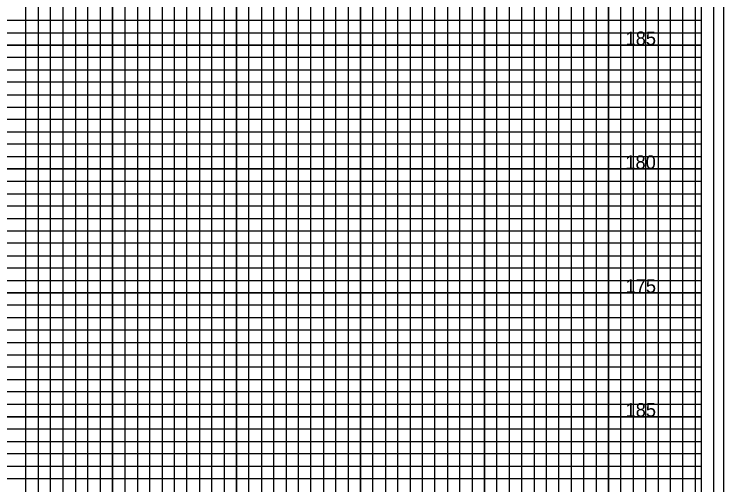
# Model space of a CAD drawing. Extents: x -4 to 103, y -2 to 280.
# Drawn here: x 74.78 to 103.4, y 173.9 to 192.9 of the extents above; entities that cross this region are included whole.
import ezdxf

# ---------------------------------------------------------------- set-up
doc = ezdxf.new("R2010")
doc.units = 0
for name, color, linetype in [('Exist XS Center Line Elevation Label', 7, 'Continuous'), ('Old_Level_63', 7, 'Continuous'), ('Prop XS Dump Level', 7, 'Continuous'), ('Prop XS SE Text', 7, 'Continuous'), ('Prop XS Subgrade Earthwork', 7, 'Continuous'), ('Sheet Plot Border Inside CELL', 7, 'Continuous'), ('Sheet Plot Border Outside CELL', 7, 'Continuous')]:
    doc.layers.add(name, color=color, linetype=linetype)

msp = doc.modelspace()

# ---------------------------------------------------------------- linework, layer by layer
at = {"layer": 'Exist XS Center Line Elevation Label'}
for points in [[(91.25, 141.65), (91.25, 205.075), (93.75, 205.075), (93.75, 141.65)], [(96.25, 141.65), (96.25, 205.075), (98.75, 205.075), (98.75, 141.65)], [(101.25, 141.65), (101.25, 205.075)], [(76.25, 141.65), (76.25, 203.65), (78.75, 203.65), (78.75, 141.65)], [(81.25, 141.65), (81.25, 203.65), (83.75, 203.65), (83.75, 141.65)], [(86.25, 141.65), (86.25, 203.65), (88.75, 203.65), (88.75, 141.65)], [(0, 189.15), (102.5, 189.15), (102.5, 191.65), (0, 191.65)], [(0, 184.15), (102.5, 184.15), (102.5, 186.65), (0, 186.65)], [(0, 179.15), (102.5, 179.15), (102.5, 181.65), (0, 181.65)], [(0, 174.15), (102.5, 174.15), (102.5, 176.65), (0, 176.65)]]:
    msp.add_lwpolyline(points, dxfattribs=at)
at = {"layer": 'Old_Level_63'}
msp.add_lwpolyline([(102.5, 206.65), (0, 206.65), (0, 141.65), (102.5, 141.65)], close=True, dxfattribs=at)
at = {"layer": 'Prop XS Dump Level'}
for p, q in [((91.25, 141.65), (91.25, 205.075)), ((93.75, 141.65), (93.75, 205.075)), ((96.25, 141.65), (96.25, 205.075)), ((98.75, 141.65), (98.75, 205.075)), ((101.25, 141.65), (101.25, 205.075)), ((76.25, 141.65), (76.25, 203.65)), ((78.75, 141.65), (78.75, 203.65)), ((81.25, 141.65), (81.25, 203.65)), ((83.75, 141.65), (83.75, 203.65)), ((86.25, 141.65), (86.25, 203.65)), ((88.75, 141.65), (88.75, 203.65)), ((0, 191.65), (102.5, 191.65)), ((0, 189.15), (102.5, 189.15)), ((0, 186.65), (102.5, 186.65)), ((0, 184.15), (102.5, 184.15)), ((0, 181.65), (102.5, 181.65)), ((0, 179.15), (102.5, 179.15)), ((0, 176.65), (102.5, 176.65)), ((0, 174.15), (102.5, 174.15))]:
    msp.add_line(p, q, dxfattribs=at)
at = {"layer": 'Prop XS SE Text'}
for points in [[(90.25, 141.65), (90.25, 205.075), (90.75, 205.075), (90.75, 141.65)], [(91.75, 141.65), (91.75, 205.075), (92.25, 205.075), (92.25, 141.65)], [(92.75, 141.65), (92.75, 205.075), (93.25, 205.075), (93.25, 141.65)], [(94.25, 141.65), (94.25, 205.075), (94.75, 205.075), (94.75, 141.65)], [(95.25, 141.65), (95.25, 205.075), (95.75, 205.075), (95.75, 141.65)], [(96.75, 141.65), (96.75, 205.075), (97.25, 205.075), (97.25, 141.65)], [(97.75, 141.65), (97.75, 205.075), (98.25, 205.075), (98.25, 141.65)], [(99.25, 141.65), (99.25, 205.075), (99.75, 205.075), (99.75, 141.65)], [(100.25, 141.65), (100.25, 205.075)], [(100.25, 205.075), (100.75, 205.075), (100.75, 141.65), (101.75, 141.65), (101.75, 205.075), (102.25, 205.075), (102.25, 141.65)], [(75.25, 141.65), (75.25, 203.65), (75.75, 203.65), (75.75, 141.65)], [(76.75, 141.65), (76.75, 203.65), (77.25, 203.65), (77.25, 141.65)], [(77.75, 141.65), (77.75, 203.65), (78.25, 203.65), (78.25, 141.65)], [(79.25, 141.65), (79.25, 203.65), (79.75, 203.65), (79.75, 141.65)], [(80.25, 141.65), (80.25, 203.65), (80.75, 203.65), (80.75, 141.65)], [(81.75, 141.65), (81.75, 203.65), (82.25, 203.65), (82.25, 141.65)], [(82.75, 141.65), (82.75, 203.65), (83.25, 203.65), (83.25, 141.65)], [(84.25, 141.65), (84.25, 203.65), (84.75, 203.65), (84.75, 141.65)], [(85.25, 141.65), (85.25, 203.65), (85.75, 203.65), (85.75, 141.65)], [(86.75, 141.65), (86.75, 203.65), (87.25, 203.65), (87.25, 141.65)], [(87.75, 141.65), (87.75, 203.65), (88.25, 203.65), (88.25, 141.65)], [(89.25, 141.65), (89.25, 203.65), (89.75, 203.65), (89.75, 141.65)], [(0, 192.15), (102.5, 192.15), (102.5, 192.65), (0, 192.65)], [(0, 190.65), (102.5, 190.65), (102.5, 191.15), (0, 191.15)], [(0, 189.65), (102.5, 189.65), (102.5, 190.15), (0, 190.15)], [(0, 188.15), (102.5, 188.15), (102.5, 188.65), (0, 188.65)], [(0, 187.15), (102.5, 187.15), (102.5, 187.65), (0, 187.65)], [(0, 185.65), (102.5, 185.65), (102.5, 186.15), (0, 186.15)], [(0, 184.65), (102.5, 184.65), (102.5, 185.15), (0, 185.15)], [(0, 183.15), (102.5, 183.15), (102.5, 183.65), (0, 183.65)], [(0, 182.15), (102.5, 182.15), (102.5, 182.65), (0, 182.65)], [(0, 180.65), (102.5, 180.65), (102.5, 181.15), (0, 181.15)], [(0, 179.65), (102.5, 179.65), (102.5, 180.15), (0, 180.15)], [(0, 178.15), (102.5, 178.15), (102.5, 178.65), (0, 178.65)], [(0, 177.15), (102.5, 177.15), (102.5, 177.65), (0, 177.65)], [(0, 175.65), (102.5, 175.65), (102.5, 176.15), (0, 176.15)], [(0, 174.65), (102.5, 174.65), (102.5, 175.15), (0, 175.15)]]:
    msp.add_lwpolyline(points, dxfattribs=at)
at = {"layer": 'Sheet Plot Border Inside CELL'}
msp.add_lwpolyline([(103, 207.65), (-2.8, 207.65), (-2.8, 140.65), (103, 140.65)], close=True, dxfattribs=at)
at = {"layer": 'Sheet Plot Border Outside CELL'}
msp.add_lwpolyline([(103.4, 209.05), (-3.5, 209.05), (-3.5, 139.225), (103.4, 139.225)], close=True, dxfattribs=at)

# ---------------------------------------------------------------- texts
at = {"layer": 'Prop XS Subgrade Earthwork'}
for s, p in [('185', (99.438, 191.65)), ('180', (99.43, 186.65)), ('175', (99.438, 181.65)), ('185', (99.438, 176.65))]:
    msp.add_text(s, height=0.55, dxfattribs=at).set_placement(p)

doc.saveas('drawing.dxf')
